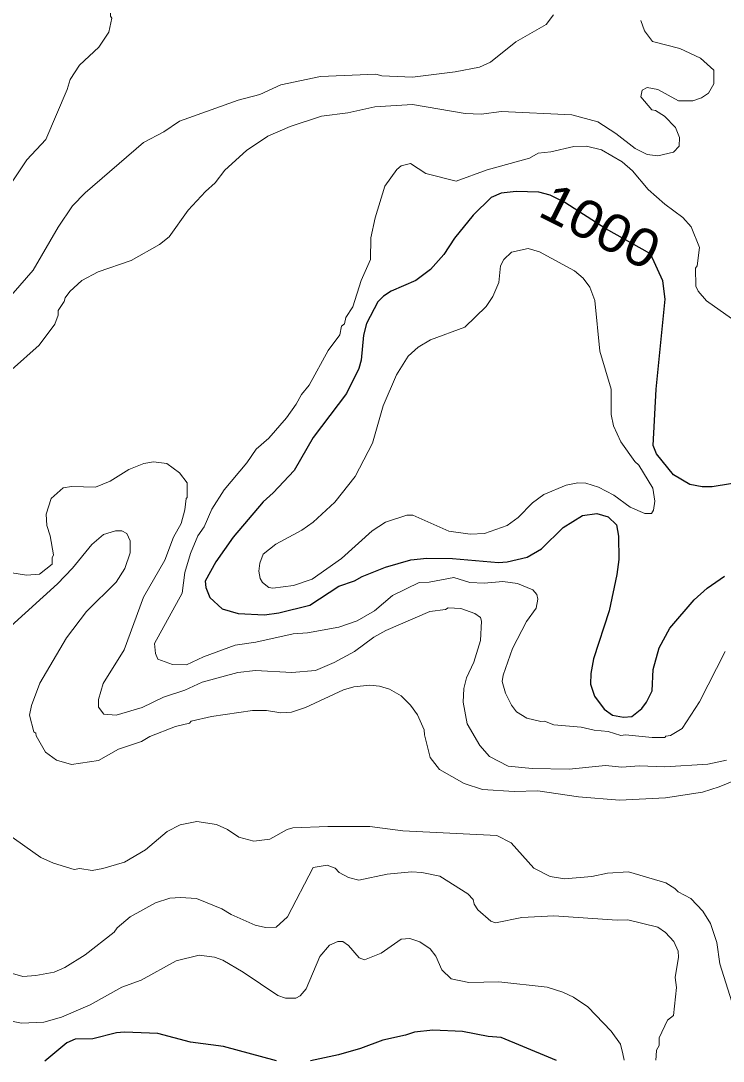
# Model space of a CAD drawing. Extents: x 447.8 to 473.9, y 7733.1 to 7760.8.
# Drawn here: x 471.4 to 472.882, y 7733.135 to 7735.329 of the extents above; entities that cross this region are included whole.
import ezdxf
from ezdxf.enums import TextEntityAlignment as Align

# ---------------------------------------------------------------- set-up
doc = ezdxf.new("R2010")
doc.units = 0
doc.header["$LTSCALE"] = 0.032
doc.layers.add('1', color=7, linetype='Continuous', lineweight=25)
doc.layers.add('2', color=7, linetype='Continuous', lineweight=13)
doc.layers.add('61', color=7, linetype='Continuous')

msp = doc.modelspace()

# ---------------------------------------------------------------- linework, layer by layer
at = {"layer": '1'}
for points in [[(472.9361, 7734.3584), (472.8592, 7734.3456), (472.8381, 7734.3455), (472.8118, 7734.3504), (472.7773, 7734.3713), (472.7412, 7734.4152), (472.7343, 7734.4332), (472.7408, 7734.5516), (472.7598, 7734.7414), (472.7549, 7734.7802), (472.7286, 7734.8369), (472.6347, 7734.8897), (472.5484, 7734.9453), (472.5174, 7734.9609), (472.4929, 7734.9675), (472.4453, 7734.969), (472.4137, 7734.965), (472.3925, 7734.956), (472.3548, 7734.9191), (472.315, 7734.8704), (472.2925, 7734.8359), (472.2648, 7734.8042), (472.2337, 7734.7813), (472.1814, 7734.7584), (472.1654, 7734.748), (472.1534, 7734.736), (472.1297, 7734.6902), (472.1234, 7734.6657), (472.1186, 7734.6132), (472.1138, 7734.5956), (472.0875, 7734.5429), (472.0172, 7734.4499), (471.977, 7734.38), (471.933, 7734.3329), (471.9116, 7734.3139), (471.8485, 7734.2396), (471.8116, 7734.1875), (471.7892, 7734.147), (471.7909, 7734.1335), (471.7992, 7734.1127), (471.8253, 7734.0882), (471.8591, 7734.0787), (471.9142, 7734.0761), (471.9447, 7734.0799), (472.0099, 7734.0963), (472.0714, 7734.1361), (472.1045, 7734.1476), (472.1203, 7734.157), (472.1696, 7734.1761), (472.2232, 7734.1916), (472.2567, 7734.1955), (472.3108, 7734.1947), (472.4079, 7734.186), (472.4267, 7734.1877), (472.4684, 7734.1975), (472.499, 7734.2153), (472.5448, 7734.2602), (472.5853, 7734.2856), (472.6158, 7734.2893), (472.6396, 7734.2828), (472.6571, 7734.266), (472.6613, 7734.2416), (472.6621, 7734.1923), (472.658, 7734.1607), (472.6413, 7734.0844), (472.6088, 7733.9834), (472.6027, 7733.9523), (472.602, 7733.9293), (472.6109, 7733.9046), (472.6311, 7733.8771), (472.6485, 7733.8645), (472.6716, 7733.8597), (472.6897, 7733.8616), (472.7104, 7733.8783), (472.7205, 7733.8915), (472.7326, 7733.9158), (472.7342, 7733.9603), (472.7472, 7734.0063), (472.7698, 7734.0475), (472.8206, 7734.1078), (472.8486, 7734.1318), (472.8852, 7734.1572)], [(471.9396, 7733.1353), (471.8281, 7733.1655), (471.7583, 7733.1743), (471.6897, 7733.1926), (471.6192, 7733.1959), (471.6025, 7733.1943), (471.5525, 7733.1817), (471.5151, 7733.1812), (471.4975, 7733.1732), (471.4512, 7733.1345)], [(472.5303, 7733.1363), (472.5139, 7733.1431), (472.4136, 7733.1847), (472.3866, 7733.1863), (472.332, 7733.1969), (472.2699, 7733.2), (472.2312, 7733.196), (472.2119, 7733.1892), (472.1644, 7733.1789), (472.1167, 7733.1613), (472.0703, 7733.1482), (472.0117, 7733.1355)]]:
    msp.add_lwpolyline(points, dxfattribs=at)
at = {"layer": '2'}
for points in [[(471.3667, 7734.9658), (471.413, 7735.0356), (471.4533, 7735.0781), (471.4981, 7735.1836), (471.5047, 7735.2047), (471.5244, 7735.2349), (471.5649, 7735.2731), (471.5863, 7735.3044), (471.5927, 7735.3342), (471.5896, 7735.3381), (471.5893, 7735.3459), (471.5558, 7735.3957), (471.5465, 7735.4205), (471.5415, 7735.4669), (471.5431, 7735.525), (471.5405, 7735.5288), (471.5398, 7735.5571), (471.535, 7735.5674), (471.5318, 7735.5954), (471.4851, 7735.6827), (471.4111, 7735.7717), (471.4038, 7735.7894), (471.3989, 7735.8148)], [(471.332, 7734.6955), (471.4265, 7734.8029), (471.4789, 7734.8931), (471.5092, 7734.9383), (471.5364, 7734.9656), (471.6591, 7735.072), (471.702, 7735.0945), (471.7355, 7735.1173), (471.8586, 7735.1613), (471.9045, 7735.1729), (471.9487, 7735.1934), (472.0329, 7735.2111), (472.1491, 7735.2159), (472.1623, 7735.2127), (472.2264, 7735.2096), (472.317, 7735.2209), (472.3678, 7735.2306), (472.3914, 7735.2417), (472.4446, 7735.2844), (472.509, 7735.3209), (472.5241, 7735.3413)], [(471.3809, 7734.5929), (471.4389, 7734.6446), (471.4724, 7734.6887), (471.4789, 7734.7081), (471.4793, 7734.7176), (471.4917, 7734.7366), (471.494, 7734.7447), (471.5037, 7734.758), (471.5288, 7734.781), (471.5636, 7734.799), (471.633, 7734.8231), (471.6933, 7734.8571), (471.7135, 7734.8734), (471.7534, 7734.9292), (471.7897, 7734.9688), (471.8105, 7734.9871), (471.8305, 7735.0136), (471.8768, 7735.055), (471.9217, 7735.0854), (471.9689, 7735.1059), (472.0349, 7735.1277), (472.0902, 7735.1347), (472.1471, 7735.147), (472.2264, 7735.1518), (472.3375, 7735.1334), (472.3719, 7735.1318), (472.4142, 7735.1374), (472.5627, 7735.1301), (472.6178, 7735.1154), (472.6555, 7735.091), (472.6968, 7735.0592), (472.7221, 7735.0468), (472.7443, 7735.0439), (472.7776, 7735.0519), (472.7892, 7735.064), (472.7903, 7735.0828), (472.7816, 7735.1036), (472.7587, 7735.1274), (472.7392, 7735.1395), (472.7318, 7735.1408), (472.7086, 7735.1682), (472.7114, 7735.1821), (472.7215, 7735.1877), (472.7446, 7735.1838), (472.7878, 7735.1597), (472.8181, 7735.1596), (472.8363, 7735.166), (472.851, 7735.1758), (472.8625, 7735.196), (472.8624, 7735.2246), (472.8346, 7735.25), (472.791, 7735.2702), (472.7333, 7735.2852), (472.7165, 7735.3076), (472.7087, 7735.3292)], [(472.9597, 7734.6586), (472.8467, 7734.7379), (472.8293, 7734.7584), (472.8248, 7734.769), (472.8241, 7734.8068), (472.8272, 7734.8122), (472.832, 7734.8504), (472.8143, 7734.8939), (472.7973, 7734.9139), (472.7594, 7734.9422), (472.7239, 7734.9732), (472.6909, 7735.0123), (472.6688, 7735.0313), (472.6255, 7735.0563), (472.5939, 7735.0645), (472.5669, 7735.0635), (472.5184, 7735.0522), (472.4916, 7735.0492), (472.4735, 7735.0387), (472.3844, 7735.0146), (472.3185, 7734.9908), (472.255, 7735.0068), (472.2227, 7735.0274), (472.2027, 7735.023), (472.1935, 7735.015), (472.1683, 7734.9799), (472.1482, 7734.9128), (472.1391, 7734.8708), (472.1379, 7734.825), (472.1184, 7734.7808), (472.1009, 7734.7251), (472.0859, 7734.7028), (472.0835, 7734.6897), (472.0771, 7734.6848), (472.0736, 7734.6661), (472.049, 7734.6334), (472.0086, 7734.56), (471.9924, 7734.5408), (471.9815, 7734.5202), (471.9609, 7734.4916), (471.9235, 7734.4486), (471.8972, 7734.4253), (471.8773, 7734.3967), (471.8295, 7734.3393), (471.8035, 7734.299), (471.7874, 7734.2612), (471.774, 7734.2426), (471.7582, 7734.2049), (471.7465, 7734.1648), (471.7406, 7734.1217), (471.6827, 7734.0151), (471.6842, 7733.9944), (471.6897, 7733.9826), (471.7207, 7733.9711), (471.7497, 7733.9701), (471.7858, 7733.9874), (471.8529, 7734.012), (471.8963, 7734.0181), (471.9752, 7734.0359), (472.0055, 7734.0378), (472.0711, 7734.0502), (472.11, 7734.063), (472.1463, 7734.0845), (472.1844, 7734.1169), (472.2405, 7734.1442), (472.2617, 7734.1451), (472.3137, 7734.1547), (472.3475, 7734.1443), (472.3778, 7734.1427), (472.4174, 7734.1459), (472.4485, 7734.1419), (472.4803, 7734.1285), (472.4888, 7734.1188), (472.4912, 7734.1086), (472.4873, 7734.0901), (472.4675, 7734.0619), (472.4375, 7734.0052), (472.4182, 7733.9483), (472.4162, 7733.9352), (472.423, 7733.911), (472.4353, 7733.8854), (472.446, 7733.8715)], [(472.8889, 7733.7694), (472.8496, 7733.7611), (472.759, 7733.7555), (472.7048, 7733.7571), (472.6682, 7733.7547), (472.6341, 7733.7578), (472.5575, 7733.7507), (472.479, 7733.7515), (472.4283, 7733.757), (472.3895, 7733.7774), (472.3686, 7733.8006), (472.3418, 7733.8463), (472.3338, 7733.8919), (472.3351, 7733.9205), (472.3406, 7733.9427), (472.3558, 7733.9763), (472.3704, 7734.0219), (472.3726, 7734.0623), (472.3701, 7734.0705), (472.3585, 7734.0786), (472.3289, 7734.0889), (472.3017, 7734.0905), (472.2962, 7734.0874), (472.2636, 7734.0827), (472.1705, 7734.0427), (472.1453, 7734.0289), (472.1045, 7733.9985), (472.0616, 7733.9753), (472.0219, 7733.9586), (471.9721, 7733.9543), (471.8952, 7733.9583), (471.8582, 7733.9541), (471.7829, 7733.9336), (471.7464, 7733.9172), (471.7015, 7733.902), (471.6566, 7733.8804), (471.6012, 7733.8645), (471.5754, 7733.8661), (471.564, 7733.8813), (471.5641, 7733.8972), (471.5738, 7733.9309), (471.6181, 7734.0018), (471.6595, 7734.1132), (471.7042, 7734.1915), (471.7228, 7734.2399), (471.7385, 7734.2682), (471.7467, 7734.2974), (471.749, 7734.3212), (471.7515, 7734.3233), (471.7514, 7734.3542), (471.7353, 7734.3751), (471.7085, 7734.395), (471.6802, 7734.3983), (471.6596, 7734.3947), (471.628, 7734.3821), (471.589, 7734.3576), (471.5582, 7734.3448), (471.5073, 7734.3463), (471.4894, 7734.3437), (471.4647, 7734.3215), (471.4542, 7734.2881), (471.4551, 7734.2646), (471.4622, 7734.2425), (471.4692, 7734.2025), (471.4662, 7734.196), (471.4662, 7734.183), (471.44, 7734.1613), (471.4126, 7734.1595), (471.3816, 7734.1646)], [(472.103, 7733.9238), (472.0812, 7733.9177), (472.0013, 7733.8803), (471.9716, 7733.8706), (471.9492, 7733.8693), (471.9185, 7733.874), (471.889, 7733.874), (471.8025, 7733.8612), (471.7601, 7733.8517), (471.756, 7733.8476), (471.7268, 7733.8402), (471.6728, 7733.819), (471.6547, 7733.8089), (471.6062, 7733.7927), (471.5645, 7733.7688), (471.5075, 7733.7603), (471.4754, 7733.7693), (471.4525, 7733.786), (471.4325, 7733.8206), (471.4321, 7733.8261), (471.4275, 7733.829), (471.419, 7733.8643), (471.423, 7733.8844), (471.4403, 7733.9316), (471.4968, 7734.0277), (471.5388, 7734.0831), (471.6016, 7734.145), (471.6199, 7734.1735), (471.6312, 7734.2063), (471.6312, 7734.2316), (471.6238, 7734.2477), (471.6137, 7734.2533), (471.6002, 7734.2531), (471.5749, 7734.245), (471.5501, 7734.2241), (471.5095, 7734.174), (471.4781, 7734.1411), (471.3795, 7734.0521)], [(472.5828, 7733.8389), (472.6102, 7733.8323), (472.6393, 7733.83), (472.6661, 7733.8213), (472.676, 7733.8228), (472.7321, 7733.8171), (472.7588, 7733.8172), (472.761, 7733.8203), (472.7713, 7733.8213), (472.7954, 7733.8361), (472.8325, 7733.8927), (472.8862, 7733.9985)], [(472.2226, 7733.8856), (472.203, 7733.9048), (472.1779, 7733.919), (472.1568, 7733.9254), (472.1369, 7733.9277), (472.103, 7733.9238)], [(472.9119, 7733.7289), (472.874, 7733.7131), (472.8382, 7733.7022), (472.7604, 7733.6896), (472.6634, 7733.685), (472.5768, 7733.6922), (472.4912, 7733.7049), (472.4413, 7733.7034), (472.3745, 7733.7075), (472.336, 7733.7204), (472.284, 7733.7495), (472.2643, 7733.7753), (472.2517, 7733.8228), (472.2513, 7733.833), (472.2372, 7733.8652), (472.2226, 7733.8856)], [(472.446, 7733.8715), (472.4681, 7733.8578), (472.4975, 7733.851), (472.5055, 7733.8516), (472.5246, 7733.8437), (472.5828, 7733.8389)], [(472.9001, 7733.26), (472.8754, 7733.3399), (472.869, 7733.3848), (472.8556, 7733.4252), (472.8394, 7733.4506), (472.8138, 7733.4779), (472.787, 7733.4915), (472.7799, 7733.4989), (472.7609, 7733.5104), (472.6822, 7733.5341), (472.638, 7733.531), (472.6048, 7733.5238), (472.5475, 7733.519), (472.5172, 7733.5237), (472.4824, 7733.5416), (472.4347, 7733.5949), (472.4043, 7733.6102), (472.2063, 7733.6203), (472.1369, 7733.6295), (472.0481, 7733.6297), (471.9744, 7733.6263), (471.9622, 7733.6234), (471.9259, 7733.603), (471.8922, 7733.5984), (471.86, 7733.6067), (471.8364, 7733.6231), (471.8129, 7733.634), (471.7718, 7733.6401), (471.7363, 7733.6328), (471.7088, 7733.6186), (471.6636, 7733.5801), (471.619, 7733.5545), (471.5735, 7733.5407), (471.5508, 7733.5367), (471.5247, 7733.5406), (471.5126, 7733.5391), (471.4694, 7733.5519), (471.4423, 7733.5639), (471.3699, 7733.6151)], [(472.7401, 7733.1366), (472.7407, 7733.1455), (472.7415, 7733.1579), (472.747, 7733.1674), (472.7472, 7733.1836), (472.7648, 7733.2208), (472.7776, 7733.2311), (472.7839, 7733.2899), (472.7808, 7733.3113), (472.788, 7733.3541), (472.7872, 7733.3664), (472.7783, 7733.3867), (472.7602, 7733.4057), (472.7444, 7733.4169), (472.6813, 7733.4324), (472.6582, 7733.4317), (472.5249, 7733.4412), (472.4573, 7733.4373), (472.4018, 7733.4262), (472.3917, 7733.43), (472.3642, 7733.4537), (472.357, 7733.4658), (472.355, 7733.4755), (472.3433, 7733.4875), (472.2843, 7733.525), (472.2465, 7733.5327), (472.2244, 7733.5342), (472.1731, 7733.5286), (472.1135, 7733.5166), (472.0916, 7733.522), (472.0719, 7733.5323), (472.0638, 7733.5415), (472.0467, 7733.5477), (472.0175, 7733.5427), (471.9632, 7733.439), (471.939, 7733.4173), (471.9163, 7733.4164), (471.8948, 7733.4217), (471.8442, 7733.4437), (471.8243, 7733.456), (471.7707, 7733.4773), (471.7374, 7733.4797), (471.7147, 7733.4781), (471.6844, 7733.4685), (471.6313, 7733.4388), (471.6038, 7733.416), (471.597, 7733.4069), (471.5364, 7733.3591), (471.4929, 7733.3324), (471.4706, 7733.3226), (471.4322, 7733.3149), (471.4048, 7733.313), (471.3828, 7733.3194)], [(471.3805, 7733.2186), (471.4015, 7733.2144), (471.4492, 7733.2168), (471.4863, 7733.227), (471.547, 7733.2531), (471.6137, 7733.2905), (471.6544, 7733.3052), (471.7281, 7733.3462), (471.7765, 7733.3578), (471.8089, 7733.3539), (471.8269, 7733.3475), (471.8695, 7733.3222), (471.9425, 7733.2728), (471.9586, 7733.2672), (471.9805, 7733.2671), (471.9898, 7733.2725), (472.0022, 7733.2871), (472.0313, 7733.3553), (472.0516, 7733.3794), (472.0689, 7733.3867), (472.0798, 7733.3867), (472.0916, 7733.3785), (472.1145, 7733.3526), (472.1257, 7733.3484), (472.1606, 7733.3622), (472.2026, 7733.3918), (472.2214, 7733.3931), (472.2422, 7733.3862), (472.2643, 7733.3717), (472.2757, 7733.3562), (472.2888, 7733.3274), (472.3082, 7733.3082), (472.3457, 7733.3005), (472.4091, 7733.3017), (472.5108, 7733.2906), (472.544, 7733.2799), (472.5666, 7733.2693), (472.5969, 7733.2491), (472.6458, 7733.1978), (472.6653, 7733.1703), (472.6702, 7733.1503), (472.6736, 7733.1365)]]:
    msp.add_lwpolyline(points, dxfattribs=at)
msp.add_lwpolyline([(472.6221, 7734.632), (472.6115, 7734.7389), (472.6011, 7734.767), (472.5869, 7734.786), (472.5683, 7734.8015), (472.4943, 7734.8411), (472.4705, 7734.8487), (472.4359, 7734.841), (472.4196, 7734.8252), (472.4121, 7734.8119), (472.4089, 7734.7769), (472.3964, 7734.7472), (472.3818, 7734.7258), (472.3369, 7734.6824), (472.2646, 7734.6556), (472.2388, 7734.6404), (472.2176, 7734.6214), (472.193, 7734.5823), (472.1647, 7734.5164), (472.1425, 7734.4382), (472.1057, 7734.3676), (472.0626, 7734.3134), (472.0172, 7734.2714), (471.9933, 7734.2547), (471.9386, 7734.2251), (471.912, 7734.2035), (471.9047, 7734.1849), (471.9023, 7734.1677), (471.9055, 7734.1526), (471.9103, 7734.1443), (471.9233, 7734.1338), (471.932, 7734.1322), (471.9759, 7734.1378), (472.0147, 7734.1508), (472.0769, 7734.1949), (472.1416, 7734.2531), (472.17, 7734.2716), (472.2148, 7734.2861), (472.2274, 7734.2861), (472.3037, 7734.2526), (472.3483, 7734.2461), (472.3786, 7734.2477), (472.4267, 7734.2646), (472.4494, 7734.281), (472.4799, 7734.3123), (472.5037, 7734.3295), (472.5508, 7734.3492), (472.5752, 7734.3542), (472.5922, 7734.3533), (472.6191, 7734.3453), (472.6514, 7734.3282), (472.6856, 7734.3032), (472.717, 7734.2893), (472.7306, 7734.2899), (472.735, 7734.2968), (472.7382, 7734.3159), (472.7337, 7734.3432), (472.7039, 7734.3916), (472.6955, 7734.3994), (472.6659, 7734.4407), (472.6507, 7734.4742), (472.6461, 7734.4987), (472.6461, 7734.5516)], close=True, dxfattribs=at)

# ---------------------------------------------------------------- texts
at = {"layer": '61', "width": 1.1}
msp.add_text('1000', height=0.08, rotation=333.213, dxfattribs=at).set_placement((472.6051, 7734.8598), align=Align.CENTER)

doc.saveas('drawing.dxf')
